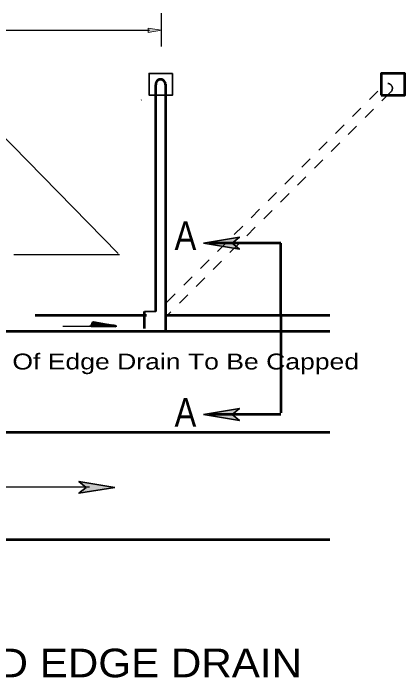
# Model space of a CAD drawing. Extents: x 72.6 to 107.3, y 36.1 to 58.1.
# Drawn here: x 93.67 to 96.95, y 43.17 to 48.74 of the extents above; entities that cross this region are included whole.
import ezdxf

# ---------------------------------------------------------------- set-up
doc = ezdxf.new("R2010")
doc.units = 0
doc.header["$LTSCALE"] = 0.053
doc.linetypes.add('DOTTED', pattern=[1.5, 0.3, -1.2])
doc.layers.add('1', color=7, linetype='Continuous', lineweight=35)
doc.layers.add('3', color=7, linetype='Continuous', lineweight=13)

msp = doc.modelspace()

# ---------------------------------------------------------------- hatches: boundary and pattern name
at = {"layer": '1'}
for points in [[(95.26433, 46.81325), (95.56433, 46.76325), (95.50433, 46.81325), (95.56433, 46.86325)], [(95.26433, 45.37725), (95.56433, 45.42725), (95.50433, 45.37725), (95.56433, 45.32725)], [(94.52083, 44.76717), (94.22083, 44.81717), (94.28083, 44.76717), (94.22083, 44.71717)]]:
    msp.add_hatch(color=256, dxfattribs=at).paths.add_polyline_path(points)
at = {"layer": '3'}
msp.add_hatch(color=256, dxfattribs=at).paths.add_polyline_path([(94.80017, 48.61617), (94.80017, 48.57867), (94.91267, 48.59742), (94.91267, 48.59742)])

# ---------------------------------------------------------------- linework, layer by layer
at = {"layer": '1', "lineweight": 25}
for p, q in [((94.91275, 48.46217), (94.91275, 48.73983)), ((91.12392, 48.5975), (94.81142, 48.5975))]:
    msp.add_line(p, q, dxfattribs=at)
at = {"layer": '1', "lineweight": 53}
for p, q in [((94.86392, 46.24175), (94.86392, 48.14)), ((94.94492, 48.145), (94.94492, 46.07475)), ((95.91267, 46.81375), (95.3095, 46.81375)), ((95.91267, 46.21058), (95.91267, 46.81375)), ((94.76892, 46.09967), (94.76892, 46.24175)), ((93.854, 46.21058), (94.786, 46.21058)), ((94.9475, 46.21058), (96.32075, 46.21058)), ((95.91267, 46.19692), (95.91267, 45.39025)), ((90.03917, 46.07475), (96.32075, 46.07475)), ((95.91267, 45.37675), (95.3095, 45.37675)), ((90.03917, 45.22958), (96.32075, 45.22958)), ((90.03917, 44.32958), (96.32075, 44.32958))]:
    msp.add_line(p, q, dxfattribs=at)
at = {"layer": '1', "linetype": 'DOTTED'}
for p, q in [((94.9565, 46.31925), (96.77558, 48.13825)), ((96.82942, 48.0775), (94.96242, 46.21058))]:
    msp.add_line(p, q, dxfattribs=at)
at = {"layer": '1'}
msp.add_line((94.76892, 46.24175), (94.86392, 46.24175), dxfattribs=at)
for points in [[(95.00525, 48.23583), (94.80825, 48.23583), (94.80825, 48.05508), (95.00525, 48.05508)], [(95.26433, 46.81325), (95.56433, 46.76325), (95.50433, 46.81325), (95.56433, 46.86325)], [(95.26433, 45.37725), (95.56433, 45.42725), (95.50433, 45.37725), (95.56433, 45.32725)], [(94.52083, 44.76717), (94.22083, 44.81717), (94.28083, 44.76717), (94.22083, 44.71717)]]:
    msp.add_lwpolyline(points, close=True, dxfattribs=at)
at = {"layer": '1', "lineweight": 53}
msp.add_lwpolyline([(96.75217, 48.05475), (96.94917, 48.05475), (96.94917, 48.2355), (96.75217, 48.2355)], close=True, dxfattribs=at)
at = {"layer": '1', "lineweight": 25}
msp.add_lwpolyline([(94.08442, 46.11775), (94.53717, 46.11775), (94.34075, 46.1525), (94.32392, 46.11833), (94.30925, 46.11783)], dxfattribs=at)
at = {"layer": '1', "lineweight": 53}
msp.add_lwpolyline([(94.32533, 46.11892), (94.34092, 46.15058), (94.52692, 46.11892), (94.32592, 46.11892), (94.3415, 46.1495), (94.51592, 46.12008), (94.32883, 46.12008), (94.342, 46.14833), (94.505, 46.12125), (94.33108, 46.12067), (94.34258, 46.14658), (94.49342, 46.12242), (94.32992, 46.12008), (94.3415, 46.14425), (94.48308, 46.1235), (94.33342, 46.12242), (94.342, 46.14258), (94.46992, 46.12525), (94.33275, 46.12175), (94.34258, 46.14025), (94.45833, 46.127), (94.33567, 46.1235), (94.34317, 46.1385), (94.44625, 46.12758), (94.338, 46.12408), (94.34433, 46.13617), (94.43358, 46.12817), (94.34025, 46.12525), (94.34542, 46.1345), (94.41167, 46.12925), (94.34433, 46.12642), (94.34542, 46.13225), (94.39267, 46.1305), (94.34717, 46.12758), (94.34717, 46.12992), (94.36792, 46.131), (94.35067, 46.12817), (94.334, 46.12175), (94.34025, 46.13567), (94.45717, 46.127), (94.36792, 46.123), (94.34542, 46.1235), (94.33858, 46.123), (94.34258, 46.13392), (94.34492, 46.13675), (94.45942, 46.12642), (94.47792, 46.12525)], dxfattribs=at)
msp.add_arc((94.9044, 48.14503), 0.0405, 352.63783, 187.17803, dxfattribs=at)
at = {"layer": '1', "linetype": 'DOTTED'}
msp.add_arc((96.8058, 48.11094), 0.04049, 305.12086, 136.088, dxfattribs=at)
at = {"layer": '1'}
msp.add_arc((94.77393, 47.9871), 0.04049, 136.63203, 140.96336, dxfattribs=at)
msp.add_arc((94.77393, 47.9871), 0.04049, 136.63203, 140.96336, dxfattribs=at)
at = {"layer": '3', "lineweight": 25}
for p, q in [((94.54842, 46.72575), (93.206, 48.09758)), ((94.55925, 46.71483), (93.67658, 46.71483)), ((94.30883, 44.77008), (93.42617, 44.77008))]:
    msp.add_line(p, q, dxfattribs=at)
at = {"layer": '3'}
msp.add_lwpolyline([(94.80017, 48.61617), (94.80017, 48.57867), (94.91267, 48.59742), (94.91267, 48.59742)], close=True, dxfattribs=at)

# ---------------------------------------------------------------- texts
for s, height, width, p in [('A', 0.24, 0.85, (95.02175, 46.75667)), ('End Of Edge Drain To Be Capped', 0.133, 1.25, (93.20575, 45.755)), ('A', 0.24, 0.85, (95.02175, 45.27517)), ('PREFABRICATED EDGE DRAIN', 0.24, 1.1, (90.83225, 43.17533))]:
    msp.add_text(s, height=height, dxfattribs=dict(at, width=width)).set_placement(p)

doc.saveas('drawing.dxf')
